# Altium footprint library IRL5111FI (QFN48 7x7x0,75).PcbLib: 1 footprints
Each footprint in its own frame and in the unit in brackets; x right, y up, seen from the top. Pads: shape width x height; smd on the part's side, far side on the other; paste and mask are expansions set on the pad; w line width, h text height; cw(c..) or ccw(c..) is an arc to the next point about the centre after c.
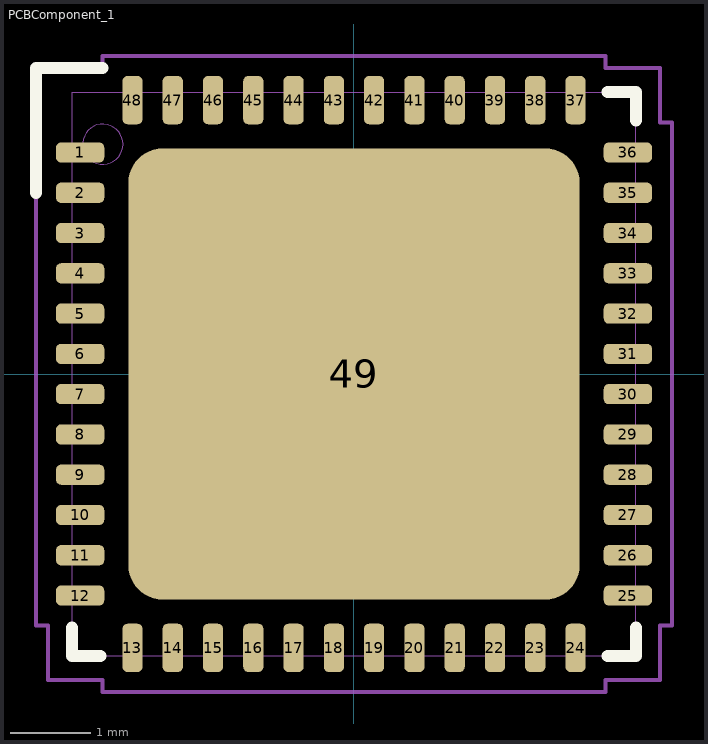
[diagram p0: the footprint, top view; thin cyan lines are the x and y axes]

## PCBComponent_1 [mm]
pads (49):
  rrect50% 0.6x0.25 smd mask+0.05: 1(-3.4,2.75) 2(-3.4,2.25) 3(-3.4,1.75) 4(-3.4,1.25) 5(-3.4,0.75) 6(-3.4,0.25) 7(-3.4,-0.25) 8(-3.4,-0.75) 9(-3.4,-1.25) 10(-3.4,-1.75) 11(-3.4,-2.25) 12(-3.4,-2.75) 25(3.4,-2.75) 26(3.4,-2.25) 27(3.4,-1.75) 28(3.4,-1.25) 29(3.4,-0.75) 30(3.4,-0.25) 31(3.4,0.25) 32(3.4,0.75) 33(3.4,1.25) 34(3.4,1.75) 35(3.4,2.25) 36(3.4,2.75)
  rrect50% 0.25x0.6 smd mask+0.05: 13(-2.75,-3.4) 14(-2.25,-3.4) 15(-1.75,-3.4) 16(-1.25,-3.4) 17(-0.75,-3.4) 18(-0.25,-3.4) 19(0.25,-3.4) 20(0.75,-3.4) 21(1.25,-3.4) 22(1.75,-3.4) 23(2.25,-3.4) 24(2.75,-3.4) 37(2.75,3.4) 38(2.25,3.4) 39(1.75,3.4) 40(1.25,3.4) 41(0.75,3.4) 42(0.25,3.4) 43(-0.25,3.4) 44(-0.75,3.4) 45(-1.25,3.4) 46(-1.75,3.4) 47(-2.25,3.4) 48(-2.75,3.4)
  rrect15% 5.6x5.6 smd paste-2539.97 mask+0.05: 49(0,0)
Top Overlay:
  lines w0.15: -3.95,2.25 -3.95,3.8 -3.12,3.8 ; -3.5,-3.15 -3.5,-3.5 -3.15,-3.5 ; 3.15,-3.5 3.5,-3.5 3.5,-3.15 ; 3.15,3.5 3.5,3.5 3.5,3.15
Top Paste:
  drawing of 16 lines, arcs and shapes, not listed
Top Assembly:
  circle w0: c-3.117,2.853 r0.25
  lines w0: -3.5,-3.5 -3.5,3.5 3.5,3.5 3.5,-3.5 -3.5,-3.5
  text ".Designator" at -2.064,-0.28 h1.2
Top Courtyard:
  lines w0.05: -3.95,-3.12 -3.95,3.8 -3.8,3.8 -3.12,3.8 -3.12,3.95 3.12,3.95 3.12,3.8 3.8,3.8 3.8,3.12 3.95,3.12 3.95,-3.12 3.8,-3.12 3.8,-3.8 3.12,-3.8 3.12,-3.95 -3.12,-3.95 -3.12,-3.8 -3.8,-3.8 -3.8,-3.12 -3.95,-3.12
3D body "QFN-48_SQR_7_5_1x5_1.STEP": height 0.9, standoff 0, extent -3.501,-3.501 3.501,3.501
